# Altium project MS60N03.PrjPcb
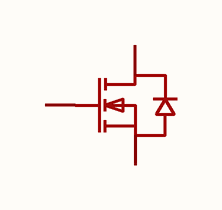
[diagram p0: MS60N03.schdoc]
1 sheet, 1 parts. Net scope: global (net labels, ports and power ports of the same name join across sheets).

## Sheet MS60N03.schdoc
size 127 x 101 mm

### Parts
Q?  ms60n03  [TO-252-2_L6.6-W6.1-P4.58-LS9.9-BR]  (value not drawn)

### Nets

Not connected (* = marked no-connect by the designer): Q? 1(G) 2(D) 3(S)

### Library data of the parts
Q? = ms60n03: 数量:1个N沟道;漏源电压(Vdss):30V;连续漏极电流(Id):60A;导通电阻(RDS(on)):6.5mΩ@10V;耗散功率(Pd):34W;阈值电压(Vgs(th)):1.5V;; Manufacturer: MSKSEMI(美森科); AddInBom: yes; ModelId: ce57f84d66384067af8a68020b6de06d; ModelName: TO-252-2L-3P_L6.6-W6.1-H2.3-LS10.1-P4.6; ModelTransform: 259.842,390.52442,0,90,0,0,-39.375,0,0; Number: 1个N沟道; Drain to Source Voltage: 30V; Current - Continuous Drain(Id): 60A; Pd - Power Dissipation: 34W; Gate Threshold Voltage (Vgs(th)): 1.5V; Gate Charge(Qg): 28nC@10V; Input Capacitance(Ciss): 920pF; Reverse Transfer Capacitance (Crss@Vds): 114pF; Type: N沟道; Output Capacitance(Coss): 198pF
